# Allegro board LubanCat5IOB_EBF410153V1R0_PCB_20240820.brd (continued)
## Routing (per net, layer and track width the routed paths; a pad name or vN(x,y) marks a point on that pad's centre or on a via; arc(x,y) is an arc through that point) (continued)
N16810480: length 5.3
  TOP w0.114: R239.1 103.58,48.17 107.02,48.17 107.22,48.38 U26.13
N16810864: length 11
  TOP w0.114: R242.1 103.57,50.8 103.95,50.41 104.52,50.41 104.94,50.83 109.98,50.83 110.35,50.46 110.35,49.6 109.98,49.23 109.23,49.23 109.03,49.03 U26.12
N16810873: length 10.2
  TOP w0.114: U26.11 109.03,49.68 109.23,49.47 109.88,49.47 110.11,49.7 110.11,50.36 109.88,50.59 105.04,50.59 104.62,50.17 103.95,50.17 103.57,49.78 R243.1
N16814949: length 2.2
  TOP w0.152: U27.4 v1(129.22,37.25)
  BOTTOM w0.152: v1(129.22,37.25) 128.94,37.25 C188.1
N16815530: length 2.1
  TOP w0.152: U27.3 v1(129.22,34.85)
  BOTTOM w0.152: v1(129.22,34.85) 128.92,34.55 R246.1
N16823880: length 8.6
  TOP w0.152: J20.B11 4.5,49.15 5.29,49.94 6.73,49.94 7.59,49.07 10.49,49.07 10.79,49.38 R247.2
N16823920: length 9.8
  TOP w0.152: R248.2 7.74,45.22 7.02,45.94 5.81,45.94 5.47,45.59 4.32,45.59 3.76,46.15 J20.B12
N16831021: length 3.4
  TOP w0.152: Q30.1 21.05,40.76 R255.2 18.95,40.76 Q31.3
N16831025: length 2.9
  TOP w0.152: R257.1 R256.2 15.66,41.34 Q31.1
N16835418: length 5.8
  TOP w0.152: U28.4 v1(16.58,43.43)
  BOTTOM w0.152: v1(16.58,43.43) 17.06,42.95 17.93,42.95 18.17,43.19 R249.1 C194.1 R250.1
N16835549: length 2.9
  TOP w0.152: U28.5 v1(17.53,43.43)
  BOTTOM w0.152: v1(17.53,43.43) 16.88,44.08 R251.1 R252.1
N16843563: length 3.4
  TOP w0.152: U29.5 v1(154.68,53.86)
  BOTTOM w0.152: R263.1 R262.2 v1(154.68,53.86)
N16843694: length 15.4
  BOTTOM w0.173: R258.2 149.88,28.75 151.35,28.75 C209.1 152.22,27.87 U30.4 153.17,28.85 153.41,29.1 156.08,29.1 156.72,28.46 158.66,28.46 159,28.12 159,25.65 158.66,25.31 J21.2
N16843698: length 10.4
  BOTTOM w0.173: J21.3 156.48,27.85 155.87,28.46 154.02,28.46 153.67,28.12 U30.5 153.67,27.32 153.42,27.07 C208.1 151.35,27.6 149.88,27.6 R259.2
N16843753: length 6.6
  TOP w0.152: U29.4 v1(154.68,52.91)
  BOTTOM w0.152: v1(154.68,52.91) 155.12,53.35 155.12,54.22 154.95,54.4 153.64,54.4 R261.1 ; C200.2 R254.2
  BOTTOM w0.173: R254.2 R261.1
N16843960: length 5.2
  TOP w0.152: J23.1 v1(144.5,73.58)
  BOTTOM w0.152: R265.2 R264.2 144.53,73.61 v1(144.5,73.58)
N16843974: length 4.5
  TOP w0.152: J23.7 v1(142.1,73.56)
  BOTTOM w0.152: R266.2 143,74.46 v1(142.1,73.56)
N16844137: length 3.7
  TOP w0.152: J23.20 133.7,60.73 R267.1
N16844170: length 11.3
  BOTTOM w0.173: R253.2 R260.2 149.88,26.46 151.35,26.46 C207.1 152.33,25.48 153.85,25.48 154.17,25.8 U30.1 154.23,26.58 J21.7
N16844211: length 3.6
  TOP w0.152: J23.22 132.9,60.51 R268.1
N16844471: length 3.9
  TOP w0.132: J23.38 126.5,62.73 126.78,62.45 126.78,60.73 R270.1
N16844509: length 3.8
  TOP w0.132: J23.36 127.3,62.73 127.02,62.45 127.02,60.68 R269.1
N16890924: length 1.7
  TOP w0.203: v1(11.18,73.88) 11.23,73.93 U31.5
  BOTTOM w0.152: R65.1 v1(11.18,73.88)
N16890990: length 5
  TOP w0.152: U31.4 v1(12.66,74.88)
  BOTTOM w0.152: v1(12.66,74.88) 12.19,74.41 C225.1 R36.1 R271.1
N16891594: length 1.9
  TOP w0.152: U1.5 v1(17.53,55.12)
  BOTTOM w0.152: v1(17.53,55.12) 17.53,55.36 R6.1
N16891660: length 6
  TOP w0.152: U1.4 16.58,55.14 v1(16.6,55.12)
  BOTTOM w0.152: v1(16.6,55.12) 16.58,55.09 16.58,54.83 16.75,54.66 17.87,54.66 18.04,54.83 R4.1 C7.1 R7.1
N16892293: length 6.2
  TOP w0.152: U32.4 v1(16.58,49.4)
  BOTTOM w0.152: v1(16.58,49.4) 16.58,49.12 16.75,48.94 18.08,48.94 18.3,49.16 R272.1 C232.1 R274.1
N16892349: length 2.8
  TOP w0.152: U32.5 v1(17.53,49.4)
  BOTTOM w0.152: C239.1 R273.1 17.26,49.66 v1(17.53,49.4)
N16906360: length 6.2
  TOP w0.152: U35.2 119.82,34.16 120.14,34.48 121.43,34.48 121.83,34.88 122.08,34.88 C241.1 123.61,34.53 Y5.2
N16906384: length 6.9
  TOP w0.152: U35.1 119.17,34.01 119.99,34.84 121.28,34.84 121.68,35.23 122.1,35.23 C240.1 123.58,35.57 Y5.1
N16906410: length 3
  TOP w0.152: U35.7 v1(119.82,36.51)
  BOTTOM w0.152: v1(119.82,36.51) 119.38,36.07 R276.2 R277.1
N16921467: length 2.6
  TOP w0.305: R287.2 v1(141.99,25.41)
  BOTTOM w0.305: D58.1 141.99,25.4 v1(141.99,25.41)
N16921931: length 2.4
  TOP w0.305: R293.2 v1(134.24,25.41)
  BOTTOM w0.305: D60.1 134.36,25.53 v1(134.24,25.41)
N16922864: length 3
  TOP w0.152: U38.3 v1(132.51,15.5)
  BOTTOM w0.152: C247.1 131.86,15.8 132.16,15.5 v1(132.51,15.5)
N16922866: length 3.2
  TOP w0.152: U38.1 v1(129.97,15.5)
  BOTTOM w0.152: C247.2 130.86,15.8 130.55,15.5 v1(129.97,15.5)
N16922868: length 2.6
  TOP w0.152: U38.5 v1(135.05,15.5)
  BOTTOM w0.152: v1(135.05,15.5) 134.91,15.64 C248.1
N16922870: length 2.6
  TOP w0.152: U38.4 v1(133.77,15.5)
  BOTTOM w0.152: C248.2 133.91,15.64 v1(133.77,15.5)
N16922872: length 2.6
  TOP w0.152: U38.6 v1(136.31,15.5)
  BOTTOM w0.152: C246.1 136.45,15.64 v1(136.31,15.5)
N16922874: length 2.8
  TOP w0.152: U38.2 v1(131.23,18.42)
  BOTTOM w0.152: C245.1 131.86,18.17 131.61,18.42 v1(131.23,18.42)
N16935603: length 6.5
  TOP w0.173: U17.4 v1(160.01,52.91)
  BOTTOM w0.152: C128.1 R138.1 R141.1 159.62,54.88 160.45,54.05 160.45,53.35 v1(160.01,52.91)
N16935717: length 3.4
  TOP w0.173: U17.5 v1(160.01,53.86)
  BOTTOM w0.152: v1(160.01,53.86) R140.1 R139.1
N16966626: length 6.4
  BOTTOM w0.152: U40.4 10.79,84.79 C262.1 R306.2 C259.1 13.95,83.21 U39.4
N16966707: length 15.2
  TOP w0.152: U18.4 27.17,62.77 C258.1 ; C258.1 R305.2 ; C258.1 27.19,62.2 26.87,61.89 18.77,61.89 18.55,62.11 C265.1 16.95,62.75 U41.4
N16966725: length 1.3
  TOP w0.152: U18.3 21.84,62.77 R307.1
N16966842: length 1.3
  TOP w0.152: U41.3 13.21,62.77 R310.1
N16967089: length 1.5
  BOTTOM w0.152: R308.1 13.95,88.74 U39.3
N16967190: length 1.5
  BOTTOM w0.152: U40.3 10.78,88.74 R309.1
N17015969: length 1.7
  BOTTOM w0.152: R323.1 123.51,98.1 U48.3
N17016021: length 5.2
  BOTTOM w0.152: R324.2 C284.1 126.32,100.4 123.75,100.4 123.51,100.64 U48.4
N17044511: length 6
  BOTTOM w0.152: J13.55 128.58,75.77 R147.2 R148.2
N17044551: length 4.8
  BOTTOM w0.152: R145.2 129.08,76.29 J13.53
N17044654: length 2.8
  BOTTOM w0.152: J13.52 129.33,61.25 R144.1
N17044656: length 2.8
  BOTTOM w0.152: J13.56 128.33,61.26 R146.1
N17044766: length 4.9
  BOTTOM w0.132: R142.2 141.6,75.82 141.6,74.14 141.45,73.99 141.45,72.6 141.58,72.47 J13.3
N17044768: length 4.9
  BOTTOM w0.132: J13.5 141.08,72.47 141.21,72.6 141.21,74.09 141.36,74.24 141.36,75.82 R143.2
N17083881: length 4.1
  TOP w0.152: Q32.3 11.72,23.93 Q5.1 11.27,21.2 R319.2
N17083895: length 5.4
  TOP w0.152: Q32.1 12.74,23.18 12.55,23.37 12.55,25.07 12.19,25.42 R320.2 R321.1
N17085595: length 5.5
  TOP w0.173: U43.4 v1(16.58,33.72)
  BOTTOM w0.152: R322.1 C290.1 R316.1 18.04,33.61 17.71,33.28 17.02,33.28 v1(16.58,33.72)
N17085706: length 2.8
  TOP w0.173: U43.5 v1(17.53,33.72)
  BOTTOM w0.152: R317.1 R318.1 17.53,33.9 v1(17.53,33.72)
N17139366: length 15.2
  BOTTOM w0.152: R132.2 99.95,30.5 Q2.3 97.89,29.64 97.59,29.95 97.59,37.33 97.89,37.63 100.03,37.63 Q1.1
N17139370: length 2.5
  BOTTOM w0.152: R133.2 R135.1 100.9,26.76 Q2.1
N17139392: length 5.2
  TOP w0.152: D15.1 105.36,38.45 105.68,38.76 J12.1
N17140097: length 5.9
  TOP w0.152: R126.2 R130.1 2.93,88.52 C126.1 2.91,89.55 D83.2 3.25,90.9 3.25,92.53 P1.1
N17140111: length 5.9
  TOP w0.152: P1.2 3.66,92.58 3.66,90.85 D78.2 3.95,89.55 C126.2 3.94,89.53 R134.1 R136.1
N17140177: length 3.4
  TOP w0.254: R126.1 v1(1.91,86.88)
  BOTTOM w0.203: v1(1.91,86.88) C125.1 R125.2
N17141731: length 2.4
  TOP w0.381: U42.6 26.92,79.51 C278.1 v1(26.79,80.36)
  vias: v1(26.79,82.36) v1(26.79,81.36) v1(30,82.38) v1(30,81.38) v1(30,80.38)
N17141824: length 1.6
  TOP w0.381: U46.6 38.23,79.38 C307.1
  vias: v1(38.09,82.24) v1(38.09,81.24) v1(38.09,80.24) v1(41.4,82.28) v1(41.4,81.28) v1(41.4,80.28)
N17141906: length 4.3
  TOP w0.152: U42.1 R346.1 24.39,71.38 25.02,70.75 25.02,69.73 R345.2
N17141982: length 1.5
  TOP w0.203: R343.2 U42.4
N17142014: length 1.3
  TOP w0.203: C279.2 28.19,69.11 R343.1
N17142016: length 1.5
  TOP w0.203: U42.3 R344.2
N17142030: length 1.4
  TOP w0.254: R344.1 v1(26.92,69.76)
  BOTTOM w0.203: v1(26.92,69.76) 26.79,69.9 C299.2
N17142049: length 1.7
  TOP w0.381: U42.5 L19.1
N17142051: length 1.7
  TOP w0.381: U42.8 L27.1
N17142055: length 1.5
  TOP w0.152: U42.2 C302.1
N17142188: length 4.3
  TOP w0.152: R351.2 36.32,69.6 36.32,70.75 R352.1 U46.1
N17142262: length 1.3
  TOP w0.203: U46.4 R349.2
N17142284: length 1.3
  TOP w0.203: U46.3 R350.2
N17142286: length 1.4
  TOP w0.203: R349.1 C308.2
N17142298: length 1.4
  TOP w0.203: C309.2 R350.1
N17142317: length 1.8
  TOP w0.381: U46.5 L28.1
N17142331: length 1.8
  TOP w0.381: U46.8 L29.1
N17142348: length 1.3
  TOP w0.152: C312.1 U46.2
N17143919: length 8.1
  TOP w0.152: J11.6 43.28,100 D81.2 43.56,99.07 v1(43.42,98.93)
  BOTTOM w0.152: v1(43.42,98.93) 42.89,99.46 41.9,99.46 C288.1 41.39,99.95 R119.2 R120.1
N17143960: length 2.4
  TOP w0.152: J11.2 v1(32.26,98.1)
  BOTTOM w0.152: v1(32.26,98.1) 32.26,97.8 R327.1
N17143962: length 12.7
  TOP w0.152: J11.1 32.04,101 v1(31.5,100.46)
  BOTTOM w0.152: v1(31.5,100.46) 31.5,98.96 D82.2 32.5,98.95 R115.2 R116.1 33.16,100.58 36.71,100.58 C116.1 37.34,99.94 R114.1
N17143973: length 5.8
  BOTTOM w0.152: R113.1 36.7,97.04 36.7,97.79 36.32,98.17 35.57,98.17 C111.1 33.54,98.93 R115.1
N17144006: length 8.7
  TOP w0.203: v1(42.58,96.19) 43.47,96.19 43.69,95.98 D79.2 43.04,95.38 42.56,94.9 J11.4
  BOTTOM w0.203: Q3.2 41.58,95.19 v1(42.58,96.19)
N17144062: length 9
  BOTTOM w0.203: Q3.1 35.93,93.28 35.61,93.6 35.61,94.88 35.31,95.19 Q4.1 34.51,96.09 C289.1 R326.1
N17144068: length 1.3
  BOTTOM w0.203: R124.2 32.76,91.18 C287.2
N17144070: length 1.3
  BOTTOM w0.203: R122.2 38.64,90.94 C122.2
N17144072: length 3.5
  BOTTOM w0.203: R122.1 R123.1 40.64,93.16 41.06,93.58 Q3.3
N17144086: length 4.2
  BOTTOM w0.203: R124.1 R325.1 31.5,94.03 31.7,94.23 Q4.3
N17144157: length 8.4
  TOP w0.203: J11.3 32.32,95.2 31.5,94.38 31.5,92.46 D80.2 32.13,92.59 v1(32.13,92.72)
  BOTTOM w0.203: v1(32.13,92.72) 32.69,93.28 Q4.2
N17145436: length 4.2
  BOTTOM w0.152: J41.2 53.59,10.79 D25.1 R338.2
N17145440: length 4.2
  BOTTOM w0.152: J41.3 51.49,13.8 D47.1 R339.2
N17145452: length 4.2
  BOTTOM w0.152: J41.4 49.52,10.73 D48.1 R340.2
N17149601: length 3.1
  TOP w0.152: R11.2 151.76,99.69 152.28,100.21 LED1.2
N17201409: length 2
  TOP w0.152: U44.21 v1(134.34,45)
  BOTTOM w0.152: R353.2 134.37,45.03 v1(134.34,45)
N17255856: length 3.3
  BOTTOM w0.381: D49.1 106.93,66.12 R354.1
N17266822: length 4
  TOP w0.152: Q35.1 155.22,96.9 R335.1 153.28,97.53 152.39,97.53 R334.2
N17266886: length 6.4
  TOP w0.152: R128.2 153.92,101.59 154.31,101.98 156.27,101.98 LED2.2
N17266888: length 3.2
  TOP w0.152: LED2.1 155.22,99.27 155.52,98.97 Q35.3
N17604055: length 3.7
  TOP w0.152: R384.2 75.45,78.88 R385.1 75.03,78.47 U4.37
N17605387: length 4.3
  TOP w0.152: U3.37 57.25,78.47 R386.1 57.66,79.89 R387.2

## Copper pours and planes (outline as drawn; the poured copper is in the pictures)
1V05_AVDD_PHY0 on BOTTOM: 69.27,80.46 69.34,80.28 69.52,80.2 71.75,80.2 71.93,80.28 72.01,80.46 72.01,81.04 71.93,81.22 71.75,81.29 69.52,81.29 69.34,81.22 69.27,81.04
1V05_PHY0 on TOP: 74.55,71.39 76.76,71.39 76.76,73.14 76.99,73.37 77.77,73.37 77.77,73.98 74.73,73.98 74.55,73.8
1V05_PHY1 on TOP: 56.13,71.41 58.98,71.41 58.98,73.27 59.11,73.4 59.99,73.4 59.99,73.98 58.37,73.98 58.37,73.65 58.14,73.42 56.13,73.42
12V_DC on TOP: 13.34,87.39 9.7,87.39 9.35,87.75 9.35,90.08 8.89,90.54 7.62,90.54 7.16,91 7.16,94.56 7.57,94.97 9.88,94.97 10.29,94.56 10.29,92.37 10.87,91.79 12.95,91.79 13.34,91.4
GND on TOP: 119.79,76.55 133.55,76.55 133.93,76.16 133.93,71.54 133.53,71.13 120.14,71.13 119.58,71.69 119.58,74.54 119.2,74.92 119.2,77.28 119.79,77.28
GND on TOP: 68.38,50.81 59.16,50.81 58.55,50.21 58.55,39.56 58.88,39.23 64.36,39.23 64.85,39.72 64.85,48.71 65.3,49.16 68.4,49.16 68.63,49.39 68.63,50.56
GND on TOP: 164.85,68.72 165.03,68.8 165.1,68.98 165.1,73.17 164.82,73.45 164.39,73.45 164.34,73.4 162.69,73.4 162.31,73.78 162.31,78.3 162.08,78.53 157.94,78.53 157.56,78.15 157.56,68.87 157.71,68.72
GND on TOP: 121.95,33.87 123.11,33.87 123.11,33.11 125.07,33.11 125.07,37.05 123.11,37.05 123.11,36.31 121.56,36.31 121.56,38.06 124.54,38.06 124.69,38.22 124.69,38.93 124.97,39.21 128.6,39.21 128.88,38.93 128.88,31.94 121.95,31.94
GND on TOP: 54.97,22.82 54.94,22.85 54.94,35.98 55.09,36.13 67.87,36.13 68.25,36.51 68.25,44.31 68.83,44.9 77.7,44.9 77.9,44.69 77.9,35.3 74.3,35.3 73.13,34.13 73.13,26.91 74,26.04 74,25.33 73.51,24.83 73.36,24.98 71.81,24.98 70.69,23.87 70.69,22.47 68.76,22.47 68.3,22.93 64.8,22.93 64.69,22.82 63.17,22.82 63.17,25.16 63.42,25.41 65.07,25.41 66.34,26.68 66.34,33.59 65.84,34.1 57.68,34.1 56.95,33.37 56.95,23.81 55.96,22.82 ; 3 cut-outs
GND on TOP: 139.12,58.69 139.12,49.16 138.76,48.81 137.03,48.81 135.84,47.61 135.84,41.9 124.94,41.9 124.66,41.62 124.66,38.37 124.87,38.17 127.69,38.17 128.63,37.23 128.63,31.71 128.75,31.59 137.01,31.59 137.08,31.51 141.45,31.51 141.68,31.74 141.68,38.9 140.84,39.74 140.84,57.85 139.83,58.87 139.29,58.87
GND on TOP: 19.58,30.88 16.89,30.88 16.26,30.24 16.26,26.79 16.65,26.39 25.02,26.39 24.94,26.32 24.94,23.71 28.85,23.71 28.75,23.61 28.75,18 19.56,18 17.91,16.35 17.91,14.19 17.75,14.04 15.54,14.04 15.14,14.44 15.14,24.17 1.93,24.17 1.22,24.88 1.22,37.05 2.01,37.84 16.74,37.84 19.18,35.4 19.18,31.28 ; 1 cut-out
GND on TOP: 40.18,69.71 40.06,69.84 40.06,70.98 40.18,71.11 40.54,71.11 40.56,71.08 59.11,71.08 59.26,71.24 59.26,73.09 59.39,73.22 59.97,73.22 60.1,73.34 60.1,76.44 57.3,76.44 57.3,78.15 56.03,78.15 56.03,78.58 58.24,78.58 58.24,78.45 59.31,78.45 59.31,77.43 62.1,77.43 62.1,81.35 59.31,81.35 59.31,81.32 58.24,81.32 58.24,80.46 55.85,80.46 55.85,81.73 63.04,81.73 63.04,76.44 61.47,76.44 61.14,76.11 61.14,70.96 59.89,69.71
GND on TOP: 33.15,60.92 33.43,61.2 36.86,61.2 38.58,62.93 38.58,64.12 39.62,65.17 41.78,65.17 42.47,64.48 47.93,64.48 47.93,62.68 47.09,61.84 40.26,61.84 39.8,61.38 39.8,60.82 39.88,60.75 47.27,60.75 47.17,60.64 37.64,60.64 37.31,60.31 37.31,58.38 37.57,58.13 39.93,58.13 39.83,58.03 39.83,57.52 40.11,57.24 49.68,57.24 52.43,59.98 52.43,64.53 53.09,64.53 53.16,64.45 53.16,58.87 49.71,55.41 39.45,55.41 39.09,55.06 39.09,50.03 39.22,49.9 50.83,49.9 56.87,55.95 56.87,64.35 57.12,64.61 57.45,64.61 57.81,64.25 57.81,53.74 56.69,53.74 56.03,53.08 56.03,41.29 55.22,40.48 46.63,40.48 46.1,41.01 46.1,48.86 44.98,48.86 44.98,41.04 44.35,40.4 33.4,40.4 33.15,40.65 ; 7 cut-outs
GND on TOP: 111.25,42.43 111.25,39.51 122.81,39.51 122.81,42.43
GND on TOP: 117.27,68.29 117.27,61.64 116.81,61.18 116.81,52.14 116.05,51.37 100.56,51.37 100.43,51.25 100.43,50.79 98.25,50.79 94.13,46.67 79.04,46.67 77.9,45.53 77.9,44.69 77.57,44.36 77.11,44.36 76.89,44.59 76.89,45.28 77.27,45.66 77.27,53.43 78.49,53.43 78.49,48.12 78.94,47.67 94.34,47.67 99.11,52.44 105.23,52.44 116.74,63.95 116.74,68.29
GND on TOP: 27.76,62.32 27.84,62.14 28.02,62.07 29.26,62.07 29.44,62.14 29.51,62.32 29.51,63.31 29.44,63.49 29.26,63.57 28.02,63.57 27.84,63.49 27.76,63.31
GND on TOP: 12.37,45.43 12.37,42.15 15.24,42.15 15.24,45.43
GND on TOP: 161.93,63.8 162,63.62 162.18,63.55 163.19,63.55 163.37,63.62 163.45,63.8 163.45,64.87 163.37,65.05 163.19,65.12 162.18,65.12 162,65.05 161.93,64.87
GND on TOP: 152.48,63.5 152.55,63.32 152.73,63.24 157.43,63.24 157.61,63.32 157.68,63.5 157.68,64 157.33,64.35 156.57,64.35 156.31,64.61 156.31,67.05 155.96,67.41 152.73,67.41 152.55,67.34 152.48,67.16
GND on TOP: 61.57,65.5 61.57,64.07 63.53,62.12 63.53,59.81 63.14,59.43 62.33,59.43 61.87,58.97 61.87,58.89 61.42,58.43 60.58,58.43 60.38,58.64 60.38,59.83 60.1,60.11 57.66,60.11 57.3,59.76 57.3,55.67 57.68,55.29 64.36,55.29 64.72,55.64 64.72,65.17 64.39,65.5
GND on TOP: 74.98,82.41 74.98,76.44 77.88,76.44 78.16,76.16 78.16,73.17 77.95,72.96 77.17,72.96 77.17,71.34 78.54,71.34 78.82,71.62 78.82,76.16 79.1,76.44 80.72,76.44 80.72,82.41 ; 1 cut-out
GND on TOP: 157.66,80.47 157.73,80.29 157.91,80.21 159.03,80.21 159.21,80.29 159.28,80.47 159.28,84.17 159.21,84.35 159.03,84.43 157.91,84.43 157.73,84.35 157.66,84.17
GND on TOP: 144.37,75.64 145.36,76.63 145.36,77.8 144.91,77.8 144.73,77.87 144.65,78.05 144.65,82.9 142.88,82.9 142.88,83.5 142.85,83.5 142.85,83.76 142.39,84.22 142.39,86.43 142.88,86.91 142.88,87.14 143.21,87.47 143.21,87.95 143,88.15 142.88,88.15 142.88,91.38 141.96,92.29 140.08,92.29 139.55,91.76 139.55,83.1 139.45,83 138.46,83 138.3,83.15 138.3,84.19 138.1,84.39 136.07,84.39 135.94,84.27 135.94,81.52 135.23,81.52 135.23,80.89 135.94,80.89 135.94,80.36 135.76,80.18 134.52,80.18 134.26,80.43 134.26,92.78 134.75,93.26 136.37,93.26 136.37,93.23 136.4,93.26 149.17,93.26 149.58,92.85 149.58,86.89 150.7,85.77 150.7,78.41 150.16,77.88 150.16,73.86 149.81,73.51 138.71,73.51 138.13,72.92 138.13,55.87 137.57,55.31 127.38,55.31 126.19,56.5 126.19,57.62 126.52,57.95 135.48,57.95 136.14,58.61 136.14,74.87 136.92,75.64 ; 2 cut-outs
GND on TOP: 61.7,22.42 61.7,26.13 62.92,26.13 62.92,25.29 63.27,25.29 63.27,22.42
GND on TOP: 151.56,88.31 151.64,88.13 151.82,88.05 158.22,88.05 158.4,88.13 158.47,88.31 158.47,92.24 158.4,92.42 158.22,92.5 151.82,92.5 151.64,92.42 151.56,92.24
GND on TOP: 144.32,41.7 143.79,42.23 143.79,58.49 142.01,60.26 142.01,62.42 142.27,62.68 144.68,62.68 144.68,65.95 146.89,65.95 146.89,68.98 149.73,68.98 149.8,68.91 149.8,62.33 149.81,62.32 149.81,58.18 150.09,57.9 150.62,57.9 151.18,57.34 151.18,51.4 151.64,50.94 153.95,50.94 154.41,50.48 154.41,45.58 154.81,45.18 155.57,45.18 155.85,44.9 155.85,31.54 156.39,31 163.75,31 164.03,30.72 164.03,14.85 163.45,14.26 158.06,14.26 158.06,15.48 158.5,15.48 158.52,15.46 159.44,15.46 159.69,15.71 159.69,25.69 159.44,25.95 156.21,25.95 155.6,26.56 155.6,27.98 154.97,28.62 152.2,28.62 151.79,29.02 151.79,39.77 151.56,39.99 151.13,39.99 150.85,40.27 150.85,40.73 149.89,41.7
GND on TOP: 149.89,54.69 149.96,54.51 150.14,54.43 151.69,54.43 151.87,54.51 151.94,54.69 151.94,57.68 151.87,57.86 151.69,57.94 150.14,57.94 149.96,57.86 149.89,57.68
GND on TOP: 163.78,65.63 163.78,71.37 163.96,71.55 164.8,71.55 165,71.35 165,70.64 165.13,70.51 167.18,70.51 167.28,70.41 167.28,65.86 167.06,65.63
GND on TOP: 124.92,98.36 82.88,98.36 81.81,97.3 81.81,85.61 82.37,85.05 84.12,85.05 84.51,85.44 84.51,94.25 85.06,94.81 111.68,94.81 111.68,93.56 117.45,87.8 117.45,81.04 119.71,81.04 120.45,81.78 120.45,94.81 125.12,94.81 125.5,95.19 125.5,97.78
GND on TOP: 6.5,7.51 6.5,12.11 7.04,12.65 10.59,12.65 11.18,12.06 11.18,8.84 11.84,8.18 147.7,8.18 148.31,8.79 148.31,12.37 148.54,12.6 149.96,12.6 149.96,7.51
GND on TOP: 100.86,50.21 98.37,50.21 94.64,46.47 79.12,46.47 78.51,45.86 78.51,31.43 77.98,30.9 77.98,27.73 78.79,26.91 78.79,22.49 78.87,22.42 79.4,22.42 79.45,22.47 79.45,27.27 79.04,27.68 79.04,42.92 80.59,44.46 96.98,44.46 97.74,45.23 97.74,47.79 98.42,48.48 101.22,48.48 101.22,49.85
GND on TOP: 9.6,82.39 9.6,76.09 9.91,75.78 12.88,75.78 12.88,77.36 12.37,77.87 12.37,81.83 11.81,82.39
GND on TOP: 10.39,91.13 10.34,91.18 10.34,94.59 0.61,94.59 0.58,94.56 0.51,94.64 0.51,96.39 3.35,96.39 5.18,98.22 5.18,102.28 5.39,102.49 20.12,102.49 20.12,94.43 20.75,93.79 20.75,92.06 20.56,91.87 17.78,91.87 17.58,91.67 17.58,89.32 17.3,89.04 16.72,89.04 16.52,88.84 16.52,87.37 16.31,87.16 13.92,87.16 13.56,87.52 13.56,91.13
GND on TOP: 104.17,24.12 94.34,24.12 93.6,23.38 93.6,17.9 93.17,17.46 90.86,17.46 90.32,16.93 90.32,10.61 91.36,9.57 142.14,9.57 143.23,10.66 143.23,15.51 144.07,16.35 147.5,16.35 148.34,17.19 148.34,23.99 147.37,24.96 147.37,28.74 146.66,29.45 143.08,29.45 142.19,30.34 142.19,31.87 141.71,32.35 130,32.35 129.77,32.12 122.91,32.12 122.86,32.17 116.84,32.17 116.36,31.69 116.36,29.1 115.34,28.08 111.79,28.08 110.24,26.53 104.93,26.53 104.62,26.23 104.62,24.58 ; 3 cut-outs
GND on TOP: 17.17,52.96 17.17,55.17 17.42,55.42 21.51,55.42 21.74,55.19 21.74,53.95 21.54,53.75 21.13,53.75 20.95,53.57 20.95,52.86 20.17,52.07 18.06,52.07
GND on TOP: 23.04,94.66 22.48,94.66 21.77,95.38 21.01,95.38 20.75,95.63 20.75,98.93 21.34,99.52 23.47,99.52 23.67,99.31 23.67,95.3
GND on TOP: 67.18,12.13 66.45,12.87 50.6,12.87 50.27,13.2 50.27,17.36 50.83,17.92 54.84,17.92 55.27,17.49 55.27,16.75 55.73,16.3 61.21,16.3 61.82,16.91 61.82,19.37 62.15,19.7 63.17,19.7 63.32,19.85 63.32,25.24 66.98,25.24 67.61,24.6 67.61,23.56 68.28,22.9 68.28,19.57 67.18,19.57 67.18,18.46 67.17,18.44 67.17,17.88 68.58,17.88 68.58,17.64 67.94,17.01 67.56,17.01 67.56,14.34 69.11,14.34 69.11,15.81 73.38,15.81 73.84,16.27 73.84,17.55 74.17,17.88 76.44,17.88 76.61,17.72 76.61,14.47 76.71,14.37 78.69,14.37 78.92,14.59 78.92,15.69 79.27,16.04 81.71,16.04 82.25,15.51 82.25,12.66 81.71,12.13
GND on TOP: 11.38,54.88 11.38,60.44 11.81,60.87 29.39,60.87 30.05,60.21 30.05,45.23 29.64,44.82 26.42,44.82 25.98,45.25 25.98,59.76 25.76,59.98 21.03,59.98 19.91,58.87 19.91,57.57 19.15,56.81 16.71,56.81 15.95,56.05 15.95,54.98 15.6,54.62 11.63,54.62
GND on TOP: 4.6,69.67 4.67,69.49 4.85,69.42 5.97,69.42 6.15,69.49 6.22,69.67 6.22,71.6 6.15,71.78 5.97,71.86 4.85,71.86 4.67,71.78 4.6,71.6
GND on TOP: 157.89,48.72 157.96,48.54 158.14,48.46 160.17,48.46 160.35,48.54 160.43,48.72 160.43,51.84 160.35,52.02 160.17,52.09 158.14,52.09 157.96,52.02 157.89,51.84
GND on TOP: 161.8,46.35 161.87,46.17 162.05,46.1 163.17,46.1 163.35,46.17 163.42,46.35 163.42,47.37 163.35,47.55 163.17,47.62 162.05,47.62 161.87,47.55 161.8,47.37
GND on TOP: 28.47,95.16 28.47,98.8 28.8,99.13 30.84,99.13 31.32,98.64 31.32,95.72 30.35,94.76 28.88,94.76
GND on TOP: 163.58,48.46 163.65,48.28 163.83,48.21 165.15,48.21 165.33,48.28 165.4,48.46 165.4,51.23 165.07,51.56 165.07,53.97 164.87,54.18 163.83,54.18 163.58,53.92
GND on TOP: 42.57,65.5 41.17,65.5 40.92,65.24 40.92,64.48 41.2,64.2 42.42,64.2 42.57,64.35
GND on TOP: 24.71,42.13 29.18,42.13 29.9,41.42 29.9,35.3 30.38,34.81 33.05,34.81 33.06,34.8 44.01,34.8 45.19,33.62 45.19,29.78 45.47,29.5 52.02,29.5 52.76,28.77 52.76,23.38 52.58,23.21 50.57,23.21 49.76,24.02 49.76,25.82 48.82,26.76 42.52,26.76 41.58,25.82 27.25,25.82 27,26.08 27,30.72 26.19,31.54 26.19,39.92 25.83,40.27 24.79,40.27 24.71,40.35
GND on TOP: 15.75,51.26 11.63,51.26 11.35,50.98 11.35,47.29 11.51,47.14 17.68,47.14 18.11,46.71 18.11,46.18 20.14,46.18 21.03,47.07 21.03,49.66 20.68,50.01 16.26,50.01 15.98,50.29 15.98,51.03
GND on TOP: 162.03,81.13 162.1,80.95 162.28,80.87 163.17,80.87 163.35,80.95 163.42,81.13 163.42,82.24 163.35,82.42 163.17,82.5 162.28,82.5 162.1,82.42 162.03,82.24
GND on TOP: 146.58,99.19 146.05,99.72 137.08,99.72 137.01,99.64 132.61,99.64 131.78,100.48 120.32,100.48 119.1,101.7 41.17,101.7 40.89,101.98 40.89,102.49 167.84,102.49 167.84,102.34 167.34,101.83 148.21,101.83 148.03,101.65 148.03,99.9 147.32,99.19
GND on TOP: 151.59,91.79 151.66,91.61 151.84,91.54 152.27,91.54 152.45,91.61 152.53,91.79 152.53,94.51 152.45,94.69 152.27,94.77 151.84,94.77 151.66,94.69 151.59,94.51
GND on TOP: 120.6,62.91 134.82,62.91 135.28,63.36 135.28,70.7 134.44,71.54 119.53,71.54 119.48,71.49 119.48,70.22 117.68,68.42 117.68,61.18 117.17,60.67 117.17,57.34 117.81,56.71 119.89,56.71 120.62,57.44 120.62,62.88 ; 1 cut-out
GND on TOP: 163.8,82.97 166.75,82.97 167.11,83.33 167.11,89.85 166.85,90.11 166.67,90.11 166.32,89.75 166.32,88.69 166.34,88.66 166.34,85.66 165.43,84.75 164.24,84.75 163.8,84.32
GND on TOP: 166.93,35.18 167,35 167.18,34.92 169.72,34.92 169.9,35 169.98,35.18 169.98,46.94 169.9,47.12 169.72,47.19 167.18,47.19 167,47.12 166.93,46.94
GND on TOP: 21.74,82.64 21.74,87.9 21.16,88.48 18.34,88.48 18.11,88.71 18.11,92.85 20.75,92.85 20.75,92.29 21.54,92.29 21.54,92.85 24.13,92.85 24.13,93.44 24.21,93.51 25.48,93.51 25.58,93.41 25.58,92.85 26.26,92.85 26.26,93.46 26.37,93.56 27.23,93.56 27.36,93.44 27.36,92.85 42.95,92.85 43.54,92.27 43.54,90.26 44.58,89.22 44.63,89.22 44.7,89.14 44.7,83.15 45.82,82.03 45.82,77.84 46.58,77.08 46.58,73.45 46.25,73.12 43.69,73.12 43.36,73.45 43.36,82.01 42.9,82.46 39.29,82.46 39.14,82.31 39.14,80.1 38.3,79.26 35.56,79.26 35.08,78.78 35.08,72.81 34.57,72.3 32.36,72.3 32.08,72.58 32.08,81.65 31.62,82.11 28.65,82.11 28.45,82.31 26.34,82.31 26.09,82.06 26.09,79.34 25.22,79.34 25.22,82.06 24.97,82.31 22.07,82.31 ; 2 cut-outs
GND on TOP: 3.12,14.15 3.2,13.97 3.38,13.89 11.38,13.89 11.56,13.97 11.63,14.15 11.63,21.28 11.56,21.46 11.38,21.54 3.38,21.54 3.2,21.46 3.12,21.28
GND on TOP: 41.38,67.78 41.45,67.6 41.63,67.53 42.39,67.53 42.57,67.6 42.65,67.78 42.65,68.75 42.57,68.93 42.39,69 41.63,69 41.45,68.93 41.38,68.75
GND on TOP: 153.97,54.53 154.05,54.35 154.23,54.28 157.2,54.28 157.38,54.35 157.45,54.53 157.45,57.76 157.38,57.94 157.2,58.01 154.23,58.01 154.05,57.94 153.97,57.76
GND on TOP: 152.98,49.78 153.06,49.6 153.24,49.53 155.14,49.53 155.32,49.6 155.4,49.78 155.4,51.69 155.32,51.87 155.14,51.94 153.24,51.94 153.06,51.87 152.98,51.69
GND on TOP: 148.69,7.51 148.69,12.7 148.82,12.83 159.21,12.83 159.94,13.56 165.07,13.56 165.86,14.35 165.86,30.99 166.4,31.52 170.43,31.52 171.25,32.33 171.25,88.67 170.61,89.31 170.61,96.8 172.49,96.8 172.49,9 172.05,7.95 171,7.51 ; 1 cut-out
GND on TOP: 117.25,44.59 117.25,46.37 118.87,46.37 118.87,45.54 118.95,45.36 119.13,45.29 121.41,45.29 121.59,45.36 121.67,45.54 121.67,48.94 121.59,49.12 121.41,49.2 119.13,49.2 118.95,49.12 118.87,48.94 118.87,48.4 117.25,48.4 117.25,49.71 117.32,49.89 117.5,49.96 122.05,49.96 122.43,49.58 122.43,44.97 122.05,44.59
GND on TOP: 166.88,54 166.95,53.82 167.13,53.75 169.75,53.75 169.93,53.82 170,54 170,64.34 169.93,64.52 169.75,64.59 167.13,64.59 166.95,64.52 166.88,64.34
GND on TOP: 13.44,81.7 13.44,71.36 13.92,70.88 15.8,70.88 15.98,70.7 15.98,68.59 16,68.57 19.68,68.57 21.89,66.36 23.11,66.36 23.67,65.8 23.67,65.14 20.7,65.14 19.86,64.3 9.7,64.3 9.17,63.77 9.17,62.17 9.73,61.61 21.16,61.61 22,62.45 27.15,62.45 27.23,62.52 27.23,66.39 26.24,67.38 23.62,67.38 22.66,68.34 22.66,71.34 21.92,72.07 18.82,72.07 17.81,73.09 17.12,73.09 17.12,78.09 17.65,78.63 17.65,81.45 17.4,81.7
GND on TOP: 14.81,36.78 14.88,36.6 15.06,36.52 18.97,36.52 19.15,36.6 19.23,36.78 19.23,40.11 19.15,40.29 18.97,40.36 13.5,40.36 13.06,39.92 13.06,38.12 13.28,37.9 14.81,37.9
GND on TOP: 110.9,69.51 110.97,69.33 111.15,69.26 113.03,69.26 113.21,69.33 113.28,69.51 113.28,74.08 113.21,74.26 113.03,74.34 111.15,74.34 110.97,74.26 110.9,74.08
GND on TOP: 101.63,39.77 101.7,39.59 101.88,39.51 104.32,39.51 104.5,39.59 104.57,39.77 104.57,42.81 104.5,42.99 104.32,43.07 101.88,43.07 101.7,42.99 101.63,42.81
GND on TOP: 149.1,70.08 149.17,69.9 149.35,69.82 151.76,69.82 151.94,69.9 152.02,70.08 152.02,72.82 151.94,73 151.76,73.07 149.35,73.07 149.17,73 149.1,72.82
GND on TOP: 39.27,17.69 39.34,17.51 39.52,17.44 44.48,17.44 44.66,17.51 44.73,17.69 44.73,22.44 44.66,22.62 44.48,22.7 39.52,22.7 39.34,22.62 39.27,22.44
GND on TOP: 87.53,19.45 88.29,19.45 88.29,16.78 88.19,16.68 87.91,16.68 87.81,16.78 87.81,17.36 87.53,17.64
GND on TOP: 152.37,78.43 152.45,78.25 152.63,78.18 156.34,78.18 156.52,78.25 156.59,78.43 156.59,84.17 156.52,84.35 156.34,84.43 152.63,84.43 152.45,84.35 152.37,84.17
GND on BOTTOM: 47.8,28.51 48.59,28.51 49.05,28.97 49.05,35.52 48.87,35.7 45.39,35.7 44.68,36.41 44.68,56.71 44.32,57.06 42.32,57.06 41.76,57.62 41.76,66.99 41.22,67.53 41.22,70.27 41.17,70.32 40.23,70.32 40.23,55.87 40.56,55.54 43.51,55.54 43.79,55.26 43.79,35.32 44.17,34.94 47.14,34.94 47.55,34.53 47.55,28.77
GND on BOTTOM: 10.85,84.27 10.85,84.98 8.89,84.98 8.89,84.37 8.85,84.44 8.84,84.52 8.84,89.96 8.91,90.14 9.09,90.21 11.38,90.21 11.56,90.14 11.63,89.96 11.63,87.44 10.9,87.44 10.9,84.27
GND on BOTTOM: 61.29,86.1 61.36,85.92 61.54,85.84 62.56,85.84 62.74,85.92 62.81,86.1 62.81,87.29 62.74,87.47 62.56,87.54 61.54,87.54 61.36,87.47 61.29,87.29
GND on BOTTOM: 24.97,72.74 24.97,75.45 25.22,75.71 27.36,75.71 27.61,75.45 27.61,72.99 27.36,72.74
GND on BOTTOM: 166.42,84.78 166.5,84.6 166.67,84.53 167.77,84.53 167.95,84.6 168.02,84.78 168.02,89.79 167.95,89.97 167.77,90.04 166.67,90.04 166.5,89.97 166.42,89.79
GND on BOTTOM: 163.7,48.77 163.78,48.59 163.96,48.51 165.25,48.51 165.43,48.59 165.51,48.77 165.51,50.8 165.43,50.98 165.25,51.05 163.96,51.05 163.78,50.98 163.7,50.8
GND on BOTTOM: 171.83,29.67 171.83,71.25 169.82,73.25 169.82,94.41 169.7,94.54 169.7,89.09 169.24,88.64 166.67,88.64 166.17,89.14 166.17,91.86 165.81,92.22 159.77,92.22 159.36,91.81 159.36,90.87 158.93,90.44 150.04,90.44 149.61,90.87 149.61,96.99 149.05,97.55 146,97.55 145.77,97.78 145.77,99.41 142.93,99.41 142.88,99.47 142.88,101.6 142.65,101.83 136.3,101.83 136.04,101.57 136.04,100.81 135.84,100.61 132.16,100.61 131.44,101.32 113.56,101.32 113.26,101.01 113.26,99.39 112.93,99.06 102.84,99.06 102.21,99.69 102.21,101.34 101.98,101.57 95.07,101.57 94.79,101.29 94.79,99.9 92.3,99.9 92.3,101.65 86.18,101.65 85.9,101.37 85.9,99.9 83.41,99.9 83.13,100.18 83.13,100.81 83.03,100.91 73.76,100.91 73.15,100.3 73.15,93.04 69.75,93.04 69.57,93.22 69.57,100.25 68.91,100.91 55.07,100.91 54.51,100.35 54.51,92.91 54.48,92.89 50.98,92.89 50.98,100.89 50.32,101.55 38.86,101.55 38.86,102.49 167.61,102.49 167.61,96.93 172.49,96.93 172.49,29.67 ; 2 cut-outs
GND on BOTTOM: 49.86,75.86 54.56,75.86 54.56,80.94 49.86,80.94
GND on BOTTOM: 165.2,80.85 165.28,80.67 165.46,80.59 167.11,80.59 167.29,80.67 167.36,80.85 167.36,81.86 167.29,82.04 167.11,82.12 165.46,82.12 165.28,82.04 165.2,81.86
GND on BOTTOM: 126.77,73.68 126.85,73.5 127.03,73.43 127.76,73.43 127.94,73.5 128.02,73.68 128.02,74.55 127.94,74.73 127.76,74.8 127.03,74.8 126.85,74.73 126.77,74.55
GND on BOTTOM: 82.7,47.31 82.7,64.61 82.25,65.06 76.45,65.06 76.07,64.68 76.07,55.11 77.22,53.96 77.22,47.44 77.88,46.78 82.17,46.78 ; 1 cut-out
GND on BOTTOM: 122.5,33.85 122.15,34.2 122.15,37.91 122.43,38.19 125.83,38.19 126.03,38.39 126.03,38.78 126.34,39.08 128.27,39.08 128.96,38.39 128.96,36.97 128.68,36.97 128.68,33.92 128.6,33.85
GND on BOTTOM: 140.72,96.9 140.79,96.72 140.97,96.65 143.13,96.65 143.31,96.72 143.38,96.9 143.38,99.34 143.31,99.52 143.13,99.59 140.97,99.59 140.79,99.52 140.72,99.34
GND on BOTTOM: 55.85,15.05 55.12,15.79 53.67,15.79 52.35,17.11 52.35,17.19 40.01,17.19 38,19.19 38,47.51 37.57,47.94 37.57,52.21 42.16,52.21 42.16,30.27 42.62,29.81 48.95,29.81 49.05,29.71 49.05,26.2 53.06,22.19 53.06,18.38 54.28,17.16 57.33,17.16 57.73,17.57 57.73,22.21 51.97,27.98 51.97,46.19 51.56,46.6 50.29,46.6 50.06,46.83 50.06,61.79 49.73,62.12 48.62,62.12 48.34,62.4 48.34,64.33 47.19,65.47 46.61,65.47 46.28,65.8 46.28,68.09 46.51,68.32 47.68,68.32 48.08,67.91 48.08,66.33 49.38,65.04 49.89,65.04 50.24,64.68 50.24,63.31 51.18,62.37 51.18,48.38 51.59,47.97 52.65,47.97 52.93,47.69 52.93,28.74 58.47,23.21 58.47,17.39 58.24,17.16 61.54,17.16 61.95,16.75 61.95,15.05
GND on BOTTOM: 23.52,83.12 41.88,83.12 43.97,85.21 43.97,91.58 44.83,92.45 44.83,97.47 43.13,99.18 40.06,99.18 40.06,95.87 41.55,95.87 42.01,95.42 42.01,91.89 41.66,91.53 40.59,91.53 39.57,90.52 32.18,90.52 32.05,90.64 32.05,91.15 31.88,91.33 22.33,91.33 21.84,90.85 21.79,90.85 20.14,89.19 20.14,87.14 19.41,87.87 18.52,87.87 18.14,88.25 18.14,91.3 17.73,91.71 15.88,91.71 15.44,91.28 15.44,85.69 16.1,85.03 18.82,85.03 18.82,82.03 19.2,81.65 22.05,81.65
GND on BOTTOM: 73.46,43.93 73.66,44.13 73.66,56.81 74.27,57.42 74.27,65.57 73.89,65.95 73.89,70.88 74.17,71.16 76.1,71.16 76.28,70.98 76.28,65.62 75.92,65.27 75.64,65.27 75.36,64.99 75.36,54.4 74.85,53.89 74.85,45.56 75.21,45.2 76,45.2 76.25,44.95 76.25,43.98 76.17,43.91 73.48,43.91
GND on BOTTOM: 61.59,34.43 62.56,34.43 62.81,34.69 62.81,49.24 63.4,49.82 68.71,49.82 69.01,50.13 69.01,64.23 66.52,66.72 66.52,70.47 66.04,70.96 65.43,70.96 65.1,70.63 65.1,62.88 66.93,61.05 66.93,51.22 66.6,50.89 61.82,50.89 61.42,50.48 61.42,34.61
GND on BOTTOM: 166.83,34.95 166.9,34.77 167.08,34.7 169.42,34.7 169.6,34.77 169.67,34.95 169.67,46.46 169.6,46.64 169.42,46.71 167.08,46.71 166.9,46.64 166.83,46.46
GND on BOTTOM: 28.24,95.07 28.32,94.89 28.5,94.82 29.41,94.82 29.59,94.89 29.67,95.07 29.67,96.04 29.59,96.22 29.41,96.29 28.5,96.29 28.32,96.22 28.24,96.04
GND on BOTTOM: 68.22,75.81 68.22,81.8 68.48,82.06 72.82,82.06 73,81.88 73,76.24 72.57,75.81
GND on BOTTOM: 18.8,71.11 18.8,76.7 19.71,77.61 21.89,77.61 21.84,77.53 21.82,77.43 21.82,76.44 21.89,76.26 22.07,76.19 22.58,76.19 22.58,72.3 21.39,71.11
GND on BOTTOM: 7.67,72.24 4.75,72.24 4.55,72.03 4.55,69.47 4.72,69.29 5.26,69.29 5.41,69.44 5.41,70.69 5.64,70.92 7.67,70.92
GND on BOTTOM: 172.49,29.95 172.49,9 172.05,7.95 171,7.51 163.35,7.51 163.35,29.69 163.42,29.87 163.6,29.95 ; 1 cut-out
GND on BOTTOM: 152.86,49.73 152.93,49.55 153.11,49.48 155.17,49.48 155.35,49.55 155.42,49.73 155.42,51.66 155.35,51.84 155.17,51.92 153.11,51.92 152.93,51.84 152.86,51.66
GND on BOTTOM: 161.82,51.76 161.9,51.58 162.08,51.51 163.17,51.51 163.35,51.58 163.42,51.76 163.42,52.75 163.35,52.93 163.17,53.01 162.08,53.01 161.9,52.93 161.82,52.75
GND on BOTTOM: 0.51,22.12 0.51,96.32 1.98,96.32 1.98,94.39 1.4,93.8 1.4,59.61 2.06,58.95 2.06,22.4 1.78,22.12
GND on BOTTOM: 13.84,98.91 13.92,98.73 14.1,98.65 15.62,98.65 15.8,98.73 15.88,98.91 15.88,99.85 15.8,100.03 15.62,100.1 14.1,100.1 13.92,100.03 13.84,99.85
GND on BOTTOM: 11.4,13.88 11,14.29 11,21.66 10.39,22.27 6.15,22.27 5.05,23.36 5.05,37.96 5.9,38.81 14.58,38.81 15.01,39.24 15.01,40.28 15.27,40.54 24.41,40.54 24.71,40.84 24.71,41.96 24.92,42.16 29.06,42.16 29.06,44.63 20.22,44.63 20.22,45.29 19.71,45.8 17.27,45.8 17.27,44.98 17.17,44.88 15.34,44.88 15.09,44.63 11.38,44.63 11.2,44.7 11.13,44.88 11.13,53.49 10.31,54.3 10.29,54.3 10.29,59.54 10.82,60.07 11.13,60.07 11.13,60.37 11.2,60.55 11.38,60.63 26.14,60.63 26.21,60.67 26.29,60.68 26.85,60.68 27.45,61.28 31.55,61.28 31.67,61.15 31.67,57.14 32.44,56.38 32.44,41.95 33.66,40.73 33.66,23.93 32.61,22.88 32.61,19.89 31.85,19.13 30.35,19.13 29.04,17.81 25.49,17.81 24.43,16.75 24.43,14.39 23.93,13.88 ; 4 cut-outs
GND on BOTTOM: 12.67,86.73 12.67,91.3 12.19,91.79 11.43,91.79 11.13,92.09 11.13,96.18 11.48,96.53 14.07,96.53 14.3,96.31 14.3,86.88 14.15,86.73
GND on BOTTOM: outline of 182 points within 0.53,7.51 166.29,81.09 ; 2 cut-outs
GND on BOTTOM: 157.94,48.74 158.01,48.56 158.19,48.49 160.2,48.49 160.38,48.56 160.45,48.74 160.45,51.66 160.38,51.84 160.2,51.92 158.19,51.92 158.01,51.84 157.94,51.66
GND on BOTTOM: 28.5,98.69 28.57,98.51 28.75,98.44 30.58,98.44 30.76,98.51 30.84,98.69 30.84,99.13 30.76,99.31 30.58,99.38 28.75,99.38 28.57,99.31 28.5,99.13
GND on BOTTOM: 119.13,95.78 119.2,95.6 119.38,95.53 125.43,95.53 125.6,95.6 125.68,95.78 125.68,100 125.6,100.18 125.43,100.25 119.38,100.25 119.2,100.18 119.13,100
GND on BOTTOM: 33.91,101.19 33.98,101.01 34.16,100.94 36.45,100.94 36.63,101.01 36.7,101.19 36.7,102.11 36.63,102.29 36.45,102.36 34.16,102.36 33.98,102.29 33.91,102.11
GND on BOTTOM: 166.95,55.47 167.03,55.29 167.21,55.22 169.42,55.22 169.6,55.29 169.67,55.47 169.67,64.16 169.6,64.34 169.42,64.41 167.21,64.41 167.03,64.34 166.95,64.16
GND on GND02, PWR05: 3,7.51 1.24,8.24 0.51,10 0.51,100 1.24,101.76 3,102.49 170,102.49 171.76,101.76 172.49,100 172.49,10 171.76,8.24 170,7.51
GND on ART03: 67.44,58.56 63.73,62.27 59.16,62.27 58.6,62.83 58.6,67.22 63.5,67.22 63.75,66.97 67.23,66.97 70.31,63.9 76.76,63.9 77.67,64.81 82.04,64.81 82.37,65.14 82.37,69.26 82.75,69.64 87.2,69.64 87.77,70.21 87.77,71.53 87.5,71.8 82.07,71.8 80.62,70.35 80.62,67.27 79.96,66.61 76.4,66.61 75.18,65.39 69.8,65.39 68.71,66.49 68.71,74.84 68.73,74.87 68.73,82.16 69.11,82.54 77.8,82.54 78.23,82.11 78.23,78.12 78.77,77.59 78.77,76.77 78.38,76.39 72.82,76.39 72.52,76.09 72.52,75.48 105.36,75.48 106.22,76.34 106.83,76.34 109.45,78.96 111.33,78.96 116.18,83.81 133.86,83.81 134.37,84.32 150.16,84.32 150.67,83.81 150.67,80.33 164.62,80.33 164.64,80.3 167.28,80.3 167.56,80.02 167.56,79.67 165.18,77.28 165.18,75.58 163.65,74.06 163.65,72.02 162.76,71.13 159.54,71.13 157.71,72.96 145.54,72.96 143.51,70.93 120.35,70.93 116.92,67.5 116.92,60.09 115.39,58.56 ; 1 cut-out
GND on ART03: 30.2,93.66 30.2,102.4 21.62,102.4 21.62,93.66
GND on ART03: 164.16,62.6 153.87,62.6 153.44,62.17 153.44,58.49 153.03,58.08 147.45,58.08 146.2,56.83 146.2,56.3 146.23,56.28 146.23,30.72 141.38,25.87 118.29,25.87 117.6,26.56 102.44,26.56 100.15,28.84 91.11,28.84 88.82,26.56 80.62,26.56 80.06,27.12 58.85,27.12 57.81,28.16 40.46,28.16 40.01,27.7 40.01,12.61 40.74,11.88 41.81,11.88 41.81,12.79 41.33,13.27 41.33,24.48 41.76,24.91 51.28,24.91 51.97,24.22 51.97,22.34 52.3,22.01 65.07,22.01 65.41,22.34 65.41,24.27 64.77,24.91 64.77,25.8 65.07,26.1 73.96,26.1 74.3,25.77 101.12,25.77 102.16,24.73 146.33,24.73 146.76,25.16 146.76,28.59 147.62,29.45 147.62,55.36 148.29,56.02 152.25,56.02 153.59,57.37 154.91,57.37 155.4,57.85 155.4,61.43 155.75,61.79 163.88,61.79 164.52,61.15 164.52,56.2 163.58,55.26 163.58,49.82 163.83,49.57 168.1,49.57 168.88,50.36 168.88,66 168.28,66 167.64,65.37 164.87,65.37 164.49,64.99 164.49,62.93
GND on ART03: 41.45,7.51 41.45,12.66 41.68,12.89 41.78,12.89 46.35,8.32 154.66,8.32 159.6,13.26 159.6,33.56 160.12,34.08 164.52,34.08 165.07,34.64 165.07,43.86 164.64,44.29 155.32,44.29 155.17,44.44 155.17,46.12 155.42,46.37 161.06,46.37 161.42,46.01 163.35,46.01 163.98,46.65 170.33,46.65 170.89,46.09 170.89,31.67 171.3,32.08 171.3,89.28 169.85,90.73 168.61,90.73 168.15,91.18 168.15,96.26 168.55,96.67 172.49,96.67 172.49,10 171.76,8.24 170,7.51
GND on ART03: 3,7.51 1.24,8.24 0.51,10 0.51,28.06 24.28,28.06 25.53,29.3 25.53,34.89 26.24,35.6 45.67,35.6 46.71,34.56 46.71,32.02 46.41,31.71 33.96,31.71 33.63,31.38 33.63,29.81 34.14,29.3 38.13,29.3 38.58,28.84 38.58,14.9 41.12,12.36 41.33,12.36 41.76,11.93 41.76,7.51
GND on ART03: 122,102.49 170,102.49 171.76,101.76 172.49,100 172.49,88.41 171.65,87.57 167.94,87.57 167.26,86.88 167.26,83.43 166.85,83.02 132.69,83.02 133.38,83.71 133.38,86.02 132.51,86.88 122.86,86.88 122.35,87.39 118.52,87.39 118.52,98.47 119,98.95 120.5,98.95 122,100.45
GND on ART03: outline of 101 points within 0.51,60.9 64.74,95.88 ; 2 cut-outs
GND on ART03: 155.91,66.94 157.38,66.94 157.86,66.46 163.68,66.46 164.31,65.83 167.28,65.83 167.94,66.49 167.94,71.72 168.45,72.23 168.45,79.09 168.1,79.44 167.23,79.44 167.23,80.3 167.34,80.41 169.93,80.41 170.26,80.08 170.26,72.23 169.06,71.03 169.06,66 167.74,64.68 160.43,64.68 159.36,65.75 155.85,65.75 155.85,66.89
GND on ART03: 5.36,71.11 5.36,69.59 6.25,69.59 6.81,69.03 6.81,65.72 7.11,65.42 8.89,65.42 9.53,64.78 12.32,64.78 12.85,64.25 12.85,59.93 13,59.78 17.55,59.78 17.88,59.45 17.88,56.89 18.31,56.45 32.28,56.45 32.94,55.79 37.85,55.79 38.79,54.85 41.3,54.85 41.45,55.01 41.45,55.89 41.35,56 39.45,56 38.79,56.66 32.99,56.66 32,57.65 20.14,57.65 19.79,58 19.79,60.64 19.38,61.05 14.02,61.05 13.77,61.31 13.77,65.62 13.11,66.28 7.67,66.28 7.57,66.39 7.57,71.06 7.52,71.11
GND on ART03: outline of 122 points within 0.51,27.35 156.21,67.2 ; 2 cut-outs
GND on ART04: 56.01,69.76 56.01,54.14 73.23,54.14 73.23,69.76
GND on ART04: 101.52,96.84 160.86,96.84 161.8,95.9 161.8,68.49 158.22,64.91 138.07,64.91 136.17,66.82 136.17,76.11 136.27,76.21 133.91,78.58 102.21,78.58 101.47,79.31 101.47,96.79
GND on ART04: 93.47,47.84 106.1,47.84 107.01,48.76 114.66,48.76 115.09,49.19 140.56,49.19 141.33,48.43 141.33,43.32 140.49,42.48 124.79,42.48 121.18,38.88 93.5,38.88 93.47,38.9
GND on ART04: 51.71,48.3 51.79,48.12 51.97,48.05 73.91,48.05 74.09,48.12 74.17,48.3 74.17,51.68 74.09,51.86 73.91,51.93 51.97,51.93 51.79,51.86 51.71,51.68
GND on ART04: 89.69,75.91 101.9,75.91 103.12,74.69 103.12,68.8 103.89,68.04 108.56,68.04 109.27,67.32 109.27,53.25 108.71,52.69 87.63,52.69 84.35,55.97 84.35,62.35 85.19,63.18 88.39,63.18 89.23,64.02 89.23,75.45
GND on ART04: 3,7.51 1.24,8.24 0.51,10 0.51,55.79 12.57,55.79 12.95,55.41 12.95,51.83 13.59,51.2 14.91,51.2 14.99,51.27 22.76,51.27 24.03,50 24.03,7.63 23.9,7.51
GND on ART04: 167.56,13.74 166.78,14.53 166.78,96.34 167.44,97 172.49,97 172.49,13.74
GND on ART04: 105.08,20.36 142.44,20.36 143.26,19.55 143.26,14.85 143.08,14.67 105.16,14.67 104.83,15 104.83,20.11
GND on ART04: 87,47.61 91.26,47.61 91.54,47.34 91.54,16.73 91.08,16.27 87.33,16.27 86.69,16.91 86.69,47.31
GND on ART04: 156.39,7.51 156.39,12.13 162.94,12.13 164.01,13.2 164.01,17.11 164.77,17.87 170.97,17.87 172.49,16.35 172.49,10 172.49,9.92 172.49,9.84 170.16,7.51 170.08,7.51 170,7.51
GND on ART04: 76.33,36.41 48.16,36.41 45.11,33.37 45.11,30.27 43.33,28.49 43.33,15.89 43.66,15.56 75.39,15.56 76.33,16.5
VBUS5V0_TYPEC on TOP: 24.69,100.85 24.69,98.77 24.92,98.54 25.17,98.54 25.35,98.72 25.35,100.22 25.5,100.37 26.72,100.37 26.9,100.19 26.9,98.72 27.08,98.54 27.41,98.54 27.61,98.74 27.61,100.85 27.38,101.08 24.92,101.08
VBUS5V0_TYPEC on BOTTOM: 15.54,86.71 15.54,90.11 15.85,90.41 15.85,97.98 15.7,98.14 14.61,98.14 14.45,97.98 14.45,90.36 14.73,90.08 14.73,86.88 14.91,86.71
VBUS5V0_TYPEC on ART04: 14.17,100.67 14.61,101.11 27.3,101.11 27.69,100.73 27.69,97.43 27.43,97.18 16.44,97.18 15.93,96.66 14.48,96.66 14.17,96.97
VCC3V3_PCIECLK on TOP: 125.68,36.29 125.68,37.61 125.88,37.81 127.43,37.81 127.64,37.61 127.64,35.73 126.92,35.73 126.36,36.29
VCC3V3_PCIECLK on BOTTOM: 125.63,36.46 125.7,36.28 125.88,36.21 127.2,36.21 127.38,36.28 127.46,36.46 127.46,37.61 127.38,37.79 127.2,37.86 125.88,37.86 125.7,37.79 125.63,37.61
VCC3V3_PCIEX4 on TOP: 0.91,49.48 0.73,49.55 0.66,49.73 0.66,53.39 0.73,53.57 0.91,53.64 6.3,53.64 6.3,53.59 6.3,52.75 6.37,52.58 6.55,52.5 6.96,52.5 6.96,50.77 6.68,50.49 4.67,50.49 3.66,49.48
VCC3V3_PCIEX4 on TOP: 22.48,44.25 26.54,44.25 26.75,44.45 26.75,44.78 26.9,44.93 28.63,44.93 28.78,44.78 28.78,42.75 28.65,42.62 26.42,42.62 26.17,42.86 22.48,42.86
VCC3V3_PCIEX4 on BOTTOM: 28.64,42.62 23.98,42.62 23.72,42.37 23.72,41.4 23.42,41.1 16.01,41.1 14.73,39.82 9.83,39.82 8.86,40.78 8.86,46.51 7.85,47.52 7.85,48.64 6.55,49.94 5.77,49.94 5.59,50.11 5.59,51.64 5.79,51.84 7.42,51.84 10.01,49.25 10.01,48.11 10.26,47.85 10.92,47.85 11.23,47.55 11.23,45.44 11.66,45.01 14.81,45.01 15.16,44.65 15.16,43.05 15.57,42.65 19.53,42.65 19.89,43 19.89,44.83 20.17,45.11 28.59,45.11 28.85,44.85 28.85,42.84
VCC4V0_SYS on TOP: 23.72,24.84 17.86,24.84 17.63,25.07 17.63,27.61 17.7,27.68 17.83,27.68 17.91,27.61 17.91,26.59 18.5,26 22.66,26 22.94,26.28 22.94,26.84 25.43,26.84 25.43,26.23 25.6,26.05 40.53,26.05 41.34,25.24 42.14,25.24 43.36,24.02 43.36,18.23 42.37,18.23 42.37,22.19 42.06,22.49 37.52,22.49 37.31,22.29 37.16,22.29 36.96,22.49 34.9,22.49 33.76,23.64 27.2,23.64 27.03,23.46 27.03,20.13 26.85,19.95 24.05,19.95 24.03,19.98 24.03,24.54
VCC5V0_HDMI_RX on TOP: 122.35,80.39 122.35,76.76 122.2,76.61 120.32,76.61 120.22,76.71 120.22,77.27 121.01,77.27 121.13,77.39 121.13,80.01 120.9,80.24 120.9,80.42 121.03,80.54 122.2,80.54
VCC5V0_USB20_HOST on BOTTOM: 125.12,99.57 125.12,98.2 124.79,97.87 124.79,96.24 125.5,96.24 125.73,96.47 125.73,99.57
VCC5V0_USB20_HUB on BOTTOM: 141.73,98.35 141.73,99.8 141.94,100 144.81,100 144.98,100.18 144.98,101.01 145.59,101.01 145.59,99.39 142.44,99.39 142.34,99.29 142.34,98.35
VCC5V0_USB30_OTG on BOTTOM: 121.79,99.54 121.79,98.4 121.36,97.97 121.36,96.21 121.97,96.21 121.97,97.92 122.4,98.35 122.4,99.54
VCC5V0_USB_S0 on TOP: 22.48,56.31 26.47,56.31 26.82,56.67 26.82,57.1 28.63,57.1 28.78,56.95 28.78,54.38 28.63,54.23 22.73,54.23 22.48,54.48
VCC5V0_USB_S0 on BOTTOM: 14.94,84.22 14.94,85.64 14.78,85.79 14.33,85.79 14.2,85.92 14.2,86.3 14.33,86.43 16.15,86.43 16.26,86.32 16.26,84.47 16,84.22
VCC5V0_USB_S0 on BOTTOM: 120.9,100.96 120.98,100.78 121.16,100.71 122.81,100.71 122.99,100.78 123.06,100.96 123.06,101.85 122.99,102.03 122.81,102.11 121.16,102.11 120.98,102.03 120.9,101.85
VCC5V0_USB_S0 on BOTTOM: 124.21,100.96 124.28,100.78 124.46,100.71 126.49,100.71 126.67,100.78 126.75,100.96 126.75,101.85 126.67,102.03 126.49,102.11 124.46,102.11 124.28,102.03 124.21,101.85
VCC5V0_USB_S0 on BOTTOM: 140.87,100.53 140.94,100.35 141.12,100.28 142.14,100.28 142.32,100.35 142.39,100.53 142.39,101.85 142.32,102.03 142.14,102.11 141.12,102.11 140.94,102.03 140.87,101.85
VCC5V0_USB_S0 on BOTTOM: 26.29,54.43 26.36,54.25 26.54,54.18 28.52,54.18 28.7,54.25 28.78,54.43 28.78,56.97 28.7,57.15 28.52,57.23 26.54,57.23 26.36,57.15 26.29,56.97
VCC5V0_USB_S0 on ART03: 44.91,92.78 44.91,99.3 45.47,99.86 97.87,99.86 99.03,98.69 107.37,98.69 108.18,97.88 117.75,97.88 119.02,99.15 142.01,99.15 142.34,99.48 142.34,101.59 141.96,101.97 42.14,101.97 41.15,100.98 41.15,93.03 41.4,92.78
VCC5V0_USB_S0 on ART03: 5.71,91.66 16.33,91.66 16.59,91.4 16.59,85.46 16.26,85.13 14.53,85.13 14.12,85.54 14.12,87.34 13.84,87.62 5.66,87.62 5.38,87.9 5.38,91.33
VCC5V0_USB_S0 on ART04: 14.27,85.46 14.27,92.55 14.99,93.26 38.66,93.26 39.19,93.79 39.19,97.2 39.57,97.58 44.45,97.58 44.7,97.32 44.7,91.18 44.07,90.54 29.21,90.54 28.73,91.02 21.31,91.02 21.03,90.74 21.03,85.46 20.62,85.05 14.68,85.05
VCC5V0_USB_S0 on ART04: 28.37,54.29 28.37,57.06 28.02,57.42 23.72,57.42 23.14,58 23.14,61.86 22.5,62.5 7.14,62.5 6.43,63.21 6.43,90.82 5.92,91.33 2.13,91.33 1.78,90.97 1.78,60.14 2.77,59.15 2.77,58.61 3.33,58.05 15.44,58.05 15.98,57.52 15.98,54.27 16.31,53.94 28.02,53.94
VCC12V_PCIEX4 on TOP: 23.04,40.84 23.04,38.86 23.29,38.61 28.63,38.61 28.8,38.78 28.8,39.95 28.63,40.13 24.51,40.13 24.31,40.33 24.31,40.84
VCC12V_PCIEX4 on TOP: 3.48,55.41 8.59,55.41 8.76,55.49 8.84,55.67 8.84,58.66 8.41,59.1 6.78,59.1 5.99,59.88 3.35,59.88 3.07,59.6 3.07,55.82
VCC12V_PCIEX4 on BOTTOM: 25.4,38.86 25.47,38.68 25.65,38.61 28.57,38.61 28.75,38.68 28.83,38.86 28.83,39.88 28.75,40.06 28.57,40.13 25.65,40.13 25.47,40.06 25.4,39.88
VCC12V_PCIEX4 on ART03: 4.47,59.6 1.07,59.6 0.69,59.22 0.69,29.5 1.02,29.17 24.43,29.17 24.92,29.66 24.92,35.73 25.4,36.21 28.47,36.21 28.83,36.57 28.83,40.12 28.6,40.35 21.64,40.35 21.11,39.82 21.11,35.52 20.7,35.12 5.16,35.12 4.8,35.47 4.8,59.27
VCC_1V8_S0 on TOP: 38.66,14.09 45.77,14.09 46.33,14.65 46.33,18.02 46.66,18.02 46.66,13.88 46.1,13.32 38.66,13.32 38.51,13.48 38.51,13.93
VCC_1V8_S0 on BOTTOM: 157.28,35.73 148.21,35.73 148.01,35.52 148.01,33.11 147.85,32.96 146.33,32.96 146.18,33.11 146.18,33.62 146.38,33.82 146.38,34.86 146.99,34.86 147.22,35.09 147.22,36.82 147.55,37.15 157.25,37.15 157.4,37 157.4,35.85
VCC_1V8_S0 on ART03: 76.05,39.66 76.12,39.48 76.3,39.41 77.44,39.41 77.62,39.48 77.7,39.66 77.7,39.77 77.62,39.95 77.44,40.02 76.3,40.02 76.12,39.95 76.05,39.77
VCC_1V8_S0 on ART03: 38.1,13.71 38.1,28.74 38.46,29.1 43.59,29.1 43.92,28.77 43.92,27.57 43.76,27.42 43.03,27.42 42.6,27.85 40.64,27.85 40.21,27.42 40.21,13.71 40.01,13.5 38.3,13.5
VCC_1V8_S0 on ART04: 43.26,27.57 43.33,27.39 43.51,27.32 43.66,27.32 43.84,27.39 43.92,27.57 43.92,28.64 43.84,28.82 43.66,28.89 43.51,28.89 43.33,28.82 43.26,28.64
VCC_1V8_S0 on ART04: 157.28,35.73 157.35,35.91 157.35,36.92 157.28,37.1 157.1,37.18 156.92,37.1 156.84,36.92 156.84,35.91 156.92,35.73 157.1,35.65
VCC_1V8_S0 on ART04: 95.15,37.38 95.22,37.2 95.4,37.12 96.62,37.12 96.8,37.2 96.88,37.38 96.88,37.53 96.8,37.71 96.62,37.78 95.4,37.78 95.22,37.71 95.15,37.53
VCC_1V8_S3 on TOP: 38.66,15.03 45.44,15.03 45.95,15.53 45.95,18.02 46.18,18.02 46.18,14.87 45.64,14.34 38.66,14.34 38.51,14.49 38.51,14.87
VCC_3V3_S0 on TOP: 57.78,59.22 59.18,59.22 59.41,58.99 59.41,53.08 59.05,52.72 57.23,52.72 56.95,52.44 56.95,39.61 56.34,39 47.24,39 46.96,39.28 46.96,40.1 47.27,40.4 55.5,40.4 55.73,40.63 55.73,53.53 56.13,53.94 57.28,53.94 57.61,54.27 57.61,59.04
VCC_3V3_S0 on TOP: 24.59,52.58 25.98,52.58 25.98,51.54 26.26,51.26 28.55,51.26 28.75,51.05 28.75,48.59 28.65,48.49 24.84,48.49 24.59,48.74
VCC_3V3_S0 on TOP: 132.49,76.95 132.56,76.77 132.74,76.7 134.21,76.7 134.39,76.77 134.47,76.95 134.47,77.99 134.39,78.17 134.21,78.25 132.74,78.25 132.56,78.17 132.49,77.99
VCC_3V3_S0 on TOP: 122.56,54.6 122.63,54.42 122.81,54.35 123.93,54.35 124.11,54.42 124.18,54.6 124.18,57.24 124.11,57.42 123.93,57.5 122.81,57.5 122.63,57.42 122.56,57.24
VCC_3V3_S0 on BOTTOM: 26.29,48.72 26.36,48.54 26.54,48.46 28.55,48.46 28.73,48.54 28.8,48.72 28.8,50.75 28.73,50.93 28.55,51 26.54,51 26.36,50.93 26.29,50.75
VCC_3V3_S0 on BOTTOM: 109.75,64.77 109.83,64.59 110.01,64.51 111.58,64.51 111.76,64.59 111.84,64.77 111.84,65.76 111.76,65.94 111.58,66.01 110.01,66.01 109.83,65.94 109.75,65.76
VCC_3V3_S0 on ART04: 55.65,57.75 55.27,58.13 55.27,71.08 55.47,71.29 56.08,71.29 56.54,70.83 72.29,70.83 72.8,71.34 76.83,71.34 77.42,70.75 79.58,70.75 79.81,70.53 79.81,69.76 79.58,69.53 73.36,69.53 72.26,68.44 60.5,68.44 59.87,67.81 59.87,58.38 59.23,57.75
VCC_3V3_S0 on ART04: 24.77,50.26 29.26,50.26 29.79,49.72 29.79,14.77 30.73,13.83 39.65,13.83 40.82,15 40.82,39.44 41.1,39.72 48.36,39.72 48.62,39.46 48.62,38.72 48.39,38.5 43.08,38.5 42.85,38.27 42.85,15.94 43.28,15.51 92.94,15.51 93.88,16.45 93.88,31.56 94.44,32.12 119.33,32.12 119.71,32.5 119.71,34.3 120.47,35.07 146.02,35.07 146.27,34.83 146.27,31.4 145.85,30.98 144.65,30.98 145.44,30.19 145.44,22.95 145.69,22.7 145.69,22.32 145.44,22.06 145.44,21 144.81,20.36 121.62,20.36 121.56,20.41 101.9,20.41 100.79,19.29 100.79,13.78 99.77,12.77 44.93,12.77 43.33,11.17 36.58,11.17 35.92,10.51 35.92,9.74 35.46,9.29 24.77,9.29 24.23,9.82 24.23,49.72
VCC_3V3_S3 on TOP: 19.02,86.02 17.91,86.02 17.73,85.84 17.73,83.33 17.91,83.15 18.72,83.15 18.72,84.75 18.85,84.88 19.33,84.88 19.33,85.46 19.02,85.46
VCC_3V3_S3 on TOP: 15.52,64.4 15.59,64.22 15.77,64.15 18.08,64.15 18.26,64.22 18.34,64.4 18.34,65.47 18.26,65.65 18.08,65.72 15.77,65.72 15.59,65.65 15.52,65.47
VCC_3V3_S3 on TOP: 38.63,18.07 39.95,18.07 40.74,17.29 44.42,17.29 44.75,17.62 44.75,18.02 44.96,18.02 44.96,17.29 44.48,16.8 40.44,16.8 39.75,17.49 38.61,17.49 38.48,17.62 38.48,17.92
VCC_3V3_S3 on BOTTOM: 38.48,41.14 38.56,40.96 38.73,40.88 39.75,40.88 39.93,40.96 40.01,41.14 40.01,41.24 39.93,41.42 39.75,41.49 38.73,41.49 38.56,41.42 38.48,41.24
VCC_3V3_S3 on BOTTOM: 9.19,84.22 5.99,84.22 5.74,84.47 5.74,86.96 5.94,87.16 7.24,87.16 7.44,86.96 7.44,85.84 7.87,85.41 9.19,85.41
VCC_3V3_S3 on ART03: 76.02,41.06 76.1,40.88 76.28,40.81 77.47,40.81 77.65,40.88 77.72,41.06 77.72,41.14 77.65,41.32 77.47,41.39 76.28,41.39 76.1,41.32 76.02,41.14
